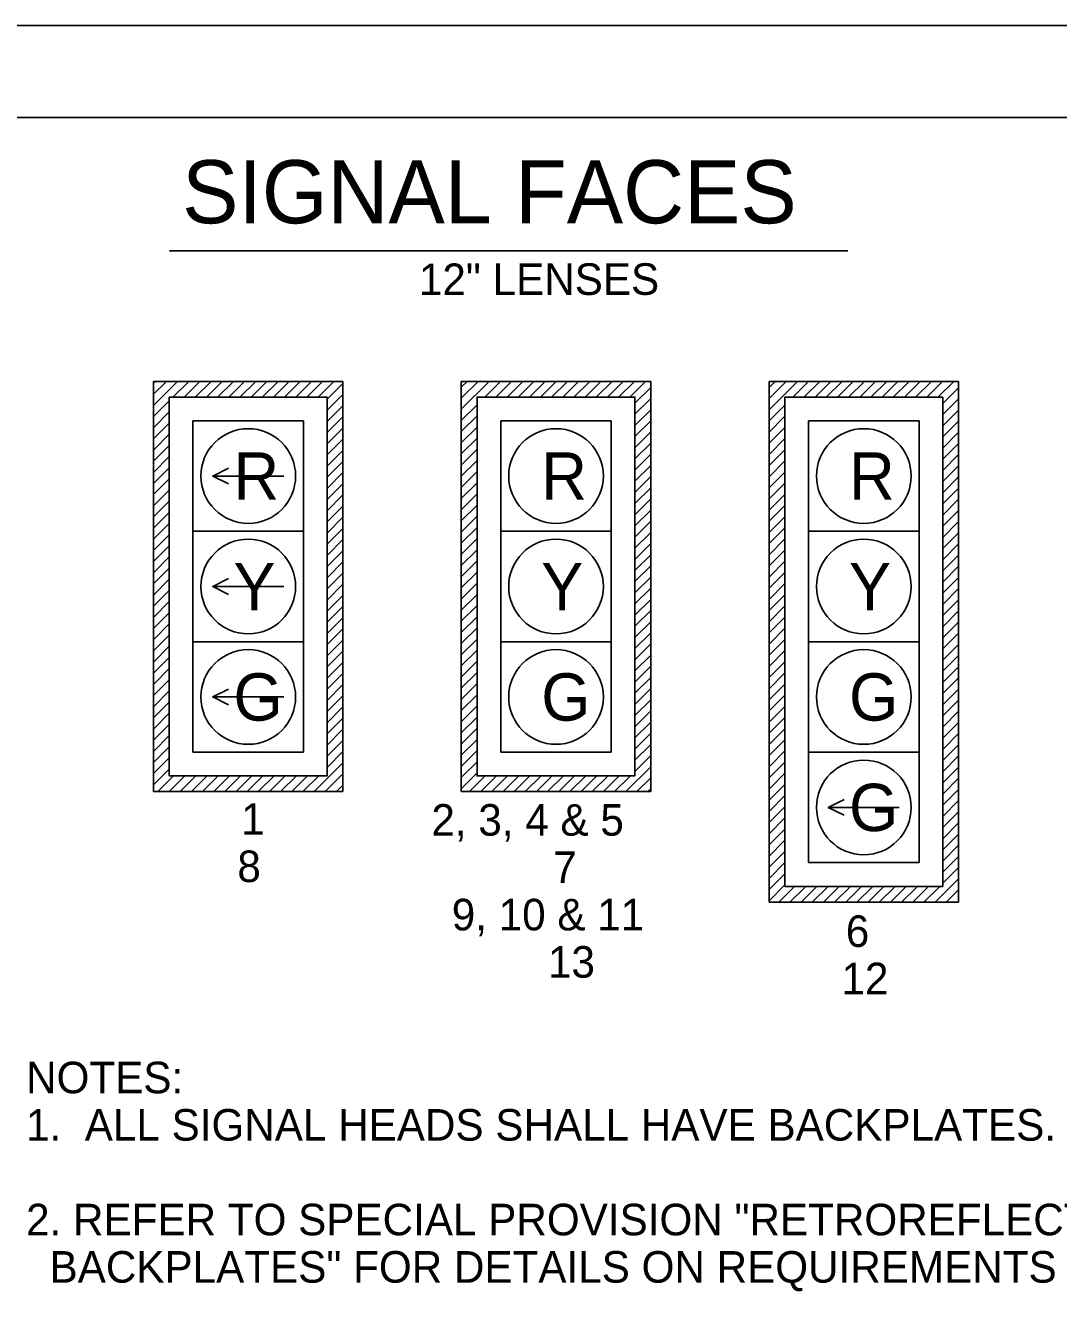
# Model space of a CAD drawing. Extents: x 660636 to 661659, y 641779 to 643841.
# Drawn here: x 660851.1 to 660982, y 642763.1 to 642924 of the extents above; entities that cross this region are included whole.
import ezdxf

# ---------------------------------------------------------------- set-up
doc = ezdxf.new("R2010")
doc.units = 0
for name, color, linetype in [('Default', 7, 'Continuous'), ('R_Border', 7, 'Continuous'), ('R_No Plot', 7, 'Continuous'), ('T_Drafting', 7, 'Continuous')]:
    doc.layers.add(name, color=color, linetype=linetype)

msp = doc.modelspace()

# ---------------------------------------------------------------- linework, layer by layer
at = {"layer": 'Default'}
msp.add_line((660869.32, 642895.44), (660955.26, 642895.44), dxfattribs=at)
at = {"layer": 'R_Border'}
msp.add_line((660695.76, 642912.31), (661644.3, 642912.31), dxfattribs=at)
at = {"layer": 'R_No Plot'}
msp.add_line((660658.55, 642924), (661658.55, 642924), dxfattribs=at)
msp.add_lwpolyline([(660658.53, 642924), (661658.55, 642924), (661658.55, 642283.98), (660658.53, 642283.98)], close=True, dxfattribs=at)
at = {"layer": 'T_Drafting'}
for p, q in [((660867.29, 642878.88), (660891.29, 642878.88)), ((660867.29, 642826.88), (660867.29, 642878.88)), ((660867.29, 642875.83), (660870.34, 642878.88)), ((660867.29, 642877.25), (660868.92, 642878.88)), ((660867.29, 642878.66), (660867.51, 642878.88)), ((660869.75, 642876.88), (660871.75, 642878.88)), ((660871.17, 642876.88), (660873.17, 642878.88)), ((660872.58, 642876.88), (660874.58, 642878.88)), ((660873.99, 642876.88), (660875.99, 642878.88)), ((660875.41, 642876.88), (660877.41, 642878.88)), ((660876.82, 642876.88), (660878.82, 642878.88)), ((660878.24, 642876.88), (660880.24, 642878.88)), ((660879.65, 642876.88), (660881.65, 642878.88)), ((660881.07, 642876.88), (660883.07, 642878.88)), ((660882.48, 642876.88), (660884.48, 642878.88)), ((660883.89, 642876.88), (660885.89, 642878.88)), ((660885.31, 642876.88), (660887.31, 642878.88)), ((660886.72, 642876.88), (660888.72, 642878.88)), ((660888.14, 642876.88), (660890.14, 642878.88)), ((660889.29, 642876.62), (660891.29, 642878.62)), ((660891.29, 642878.88), (660891.29, 642826.88)), ((660930.29, 642878.88), (660906.29, 642878.88)), ((660906.29, 642878.88), (660906.29, 642826.88)), ((660906.29, 642875.34), (660909.83, 642878.88)), ((660906.29, 642876.75), (660908.42, 642878.88)), ((660906.29, 642878.16), (660907.01, 642878.88)), ((660909.25, 642876.88), (660911.25, 642878.88)), ((660910.66, 642876.88), (660912.66, 642878.88)), ((660912.08, 642876.88), (660914.08, 642878.88)), ((660913.49, 642876.88), (660915.49, 642878.88)), ((660914.91, 642876.88), (660916.91, 642878.88)), ((660916.32, 642876.88), (660918.32, 642878.88)), ((660917.73, 642876.88), (660919.73, 642878.88)), ((660919.15, 642876.88), (660921.15, 642878.88)), ((660920.56, 642876.88), (660922.56, 642878.88)), ((660921.98, 642876.88), (660923.98, 642878.88)), ((660923.39, 642876.88), (660925.39, 642878.88)), ((660924.81, 642876.88), (660926.81, 642878.88)), ((660926.22, 642876.88), (660928.22, 642878.88)), ((660927.63, 642876.88), (660929.63, 642878.88)), ((660930.29, 642826.88), (660930.29, 642878.88)), ((660969.29, 642878.88), (660945.29, 642878.88)), ((660945.29, 642878.88), (660945.29, 642812.88)), ((660945.29, 642875.29), (660948.88, 642878.88)), ((660945.29, 642876.7), (660947.47, 642878.88)), ((660945.29, 642878.12), (660946.05, 642878.88)), ((660948.3, 642876.88), (660950.3, 642878.88)), ((660949.71, 642876.88), (660951.71, 642878.88)), ((660951.12, 642876.88), (660953.12, 642878.88)), ((660952.54, 642876.88), (660954.54, 642878.88)), ((660953.95, 642876.88), (660955.95, 642878.88)), ((660955.37, 642876.88), (660957.37, 642878.88)), ((660956.78, 642876.88), (660958.78, 642878.88)), ((660958.19, 642876.88), (660960.19, 642878.88)), ((660959.61, 642876.88), (660961.61, 642878.88)), ((660961.02, 642876.88), (660963.02, 642878.88)), ((660962.44, 642876.88), (660964.44, 642878.88)), ((660963.85, 642876.88), (660965.85, 642878.88)), ((660965.27, 642876.88), (660967.27, 642878.88)), ((660966.68, 642876.88), (660968.68, 642878.88)), ((660969.29, 642812.88), (660969.29, 642878.88)), ((660889.29, 642875.21), (660891.29, 642877.21)), ((660928.29, 642876.12), (660930.29, 642878.12)), ((660967.29, 642876.08), (660969.29, 642878.08)), ((660867.29, 642874.42), (660869.29, 642876.42)), ((660889.29, 642873.79), (660891.29, 642875.79)), ((660906.29, 642873.92), (660908.29, 642875.92)), ((660928.29, 642874.71), (660930.29, 642876.71)), ((660945.29, 642873.88), (660947.29, 642875.88)), ((660967.29, 642874.66), (660969.29, 642876.66)), ((660867.29, 642873), (660869.29, 642875)), ((660872.29, 642873.88), (660886.29, 642873.88)), ((660872.29, 642873.88), (660872.29, 642859.88)), ((660886.29, 642873.88), (660886.29, 642859.88)), ((660889.29, 642872.38), (660891.29, 642874.38)), ((660906.29, 642872.51), (660908.29, 642874.51)), ((660911.29, 642873.88), (660925.29, 642873.88)), ((660911.29, 642873.88), (660911.29, 642859.88)), ((660925.29, 642873.88), (660925.29, 642859.88)), ((660928.29, 642873.29), (660930.29, 642875.29)), ((660928.29, 642871.88), (660930.29, 642873.88)), ((660945.29, 642872.46), (660947.29, 642874.46)), ((660950.29, 642873.88), (660964.29, 642873.88)), ((660950.29, 642873.88), (660950.29, 642859.88)), ((660964.29, 642873.88), (660964.29, 642859.88)), ((660967.29, 642873.25), (660969.29, 642875.25)), ((660967.29, 642871.83), (660969.29, 642873.83)), ((660867.29, 642871.59), (660869.29, 642873.59)), ((660867.29, 642870.18), (660869.29, 642872.18)), ((660889.29, 642870.96), (660891.29, 642872.96)), ((660906.29, 642871.09), (660908.29, 642873.09)), ((660928.29, 642870.47), (660930.29, 642872.47)), ((660945.29, 642871.05), (660947.29, 642873.05)), ((660967.29, 642870.42), (660969.29, 642872.42)), ((660867.29, 642868.76), (660869.29, 642870.76)), ((660889.29, 642869.55), (660891.29, 642871.55)), ((660906.29, 642869.68), (660908.29, 642871.68)), ((660928.29, 642869.05), (660930.29, 642871.05)), ((660945.29, 642869.63), (660947.29, 642871.63)), ((660967.29, 642869.01), (660969.29, 642871.01)), ((660867.29, 642867.35), (660869.29, 642869.35)), ((660889.29, 642868.13), (660891.29, 642870.13)), ((660906.29, 642868.27), (660908.29, 642870.27)), ((660928.29, 642867.64), (660930.29, 642869.64)), ((660945.29, 642868.22), (660947.29, 642870.22)), ((660967.29, 642867.59), (660969.29, 642869.59)), ((660867.29, 642865.93), (660869.29, 642867.93)), ((660889.29, 642866.72), (660891.29, 642868.72)), ((660906.29, 642866.85), (660908.29, 642868.85)), ((660906.29, 642865.44), (660908.29, 642867.44)), ((660928.29, 642866.22), (660930.29, 642868.22)), ((660945.29, 642866.8), (660947.29, 642868.8)), ((660945.29, 642865.39), (660947.29, 642867.39)), ((660967.29, 642866.18), (660969.29, 642868.18)), ((660867.29, 642864.52), (660869.29, 642866.52)), ((660883.79, 642866.88), (660874.79, 642866.88)), ((660889.29, 642865.31), (660891.29, 642867.31)), ((660889.29, 642863.89), (660891.29, 642865.89)), ((660906.29, 642864.02), (660908.29, 642866.02)), ((660928.29, 642864.81), (660930.29, 642866.81)), ((660945.29, 642863.98), (660947.29, 642865.98)), ((660967.29, 642864.76), (660969.29, 642866.76)), ((660867.29, 642863.11), (660869.29, 642865.11)), ((660889.29, 642862.48), (660891.29, 642864.48)), ((660906.29, 642862.61), (660908.29, 642864.61)), ((660928.29, 642863.4), (660930.29, 642865.4)), ((660945.29, 642862.56), (660947.29, 642864.56)), ((660967.29, 642863.35), (660969.29, 642865.35)), ((660867.29, 642861.69), (660869.29, 642863.69)), ((660889.29, 642861.06), (660891.29, 642863.06)), ((660906.29, 642861.19), (660908.29, 642863.19)), ((660928.29, 642861.98), (660930.29, 642863.98)), ((660928.29, 642860.57), (660930.29, 642862.57)), ((660945.29, 642861.15), (660947.29, 642863.15)), ((660967.29, 642861.93), (660969.29, 642863.93)), ((660967.29, 642860.52), (660969.29, 642862.52)), ((660867.29, 642860.28), (660869.29, 642862.28)), ((660889.29, 642859.65), (660891.29, 642861.65)), ((660906.29, 642859.78), (660908.29, 642861.78)), ((660928.29, 642859.15), (660930.29, 642861.15)), ((660945.29, 642859.73), (660947.29, 642861.73)), ((660967.29, 642859.11), (660969.29, 642861.11)), ((660867.29, 642858.86), (660869.29, 642860.86)), ((660867.29, 642857.45), (660869.29, 642859.45)), ((660872.29, 642859.88), (660886.29, 642859.88)), ((660872.29, 642859.88), (660872.29, 642845.88)), ((660886.29, 642859.88), (660886.29, 642845.88)), ((660889.29, 642858.24), (660891.29, 642860.24)), ((660906.29, 642858.37), (660908.29, 642860.37)), ((660911.29, 642859.88), (660925.29, 642859.88)), ((660911.29, 642859.88), (660911.29, 642845.88)), ((660925.29, 642859.88), (660925.29, 642845.88)), ((660928.29, 642857.74), (660930.29, 642859.74)), ((660945.29, 642858.32), (660947.29, 642860.32)), ((660950.29, 642859.88), (660964.29, 642859.88)), ((660950.29, 642859.88), (660950.29, 642845.88)), ((660964.29, 642859.88), (660964.29, 642845.88)), ((660967.29, 642857.69), (660969.29, 642859.69)), ((660867.29, 642856.03), (660869.29, 642858.03)), ((660889.29, 642856.82), (660891.29, 642858.82)), ((660906.29, 642856.95), (660908.29, 642858.95)), ((660928.29, 642856.32), (660930.29, 642858.32)), ((660945.29, 642856.91), (660947.29, 642858.91)), ((660967.29, 642856.28), (660969.29, 642858.28)), ((660867.29, 642854.62), (660869.29, 642856.62)), ((660889.29, 642855.41), (660891.29, 642857.41)), ((660906.29, 642855.54), (660908.29, 642857.54)), ((660906.29, 642854.12), (660908.29, 642856.12)), ((660928.29, 642854.91), (660930.29, 642856.91)), ((660945.29, 642855.49), (660947.29, 642857.49)), ((660945.29, 642854.08), (660947.29, 642856.08)), ((660967.29, 642854.86), (660969.29, 642856.86)), ((660867.29, 642853.21), (660869.29, 642855.21)), ((660889.29, 642853.99), (660891.29, 642855.99)), ((660889.29, 642852.58), (660891.29, 642854.58)), ((660906.29, 642852.71), (660908.29, 642854.71)), ((660928.29, 642853.5), (660930.29, 642855.5)), ((660945.29, 642852.66), (660947.29, 642854.66)), ((660967.29, 642853.45), (660969.29, 642855.45)), ((660867.29, 642851.79), (660869.29, 642853.79)), ((660883.79, 642852.88), (660874.79, 642852.88)), ((660889.29, 642851.16), (660891.29, 642853.16)), ((660906.29, 642851.29), (660908.29, 642853.29)), ((660928.29, 642852.08), (660930.29, 642854.08)), ((660945.29, 642851.25), (660947.29, 642853.25)), ((660967.29, 642852.04), (660969.29, 642854.04)), ((660867.29, 642850.38), (660869.29, 642852.38)), ((660889.29, 642849.75), (660891.29, 642851.75)), ((660906.29, 642849.88), (660908.29, 642851.88)), ((660928.29, 642850.67), (660930.29, 642852.67)), ((660928.29, 642849.25), (660930.29, 642851.25)), ((660945.29, 642849.83), (660947.29, 642851.83)), ((660967.29, 642850.62), (660969.29, 642852.62)), ((660867.29, 642848.96), (660869.29, 642850.96)), ((660889.29, 642848.34), (660891.29, 642850.34)), ((660906.29, 642848.47), (660908.29, 642850.47)), ((660928.29, 642847.84), (660930.29, 642849.84)), ((660945.29, 642848.42), (660947.29, 642850.42)), ((660967.29, 642849.21), (660969.29, 642851.21)), ((660967.29, 642847.79), (660969.29, 642849.79)), ((660867.29, 642847.55), (660869.29, 642849.55)), ((660867.29, 642846.13), (660869.29, 642848.13)), ((660889.29, 642846.92), (660891.29, 642848.92)), ((660906.29, 642847.05), (660908.29, 642849.05)), ((660928.29, 642846.42), (660930.29, 642848.42)), ((660945.29, 642847.01), (660947.29, 642849.01)), ((660967.29, 642846.38), (660969.29, 642848.38)), ((660867.29, 642844.72), (660869.29, 642846.72)), ((660889.29, 642845.51), (660891.29, 642847.51)), ((660906.29, 642845.64), (660908.29, 642847.64)), ((660928.29, 642845.01), (660930.29, 642847.01)), ((660945.29, 642845.59), (660947.29, 642847.59)), ((660967.29, 642844.96), (660969.29, 642846.96)), ((660867.29, 642843.31), (660869.29, 642845.31)), ((660872.29, 642845.88), (660886.29, 642845.88)), ((660872.29, 642845.88), (660872.29, 642831.88)), ((660886.29, 642845.88), (660886.29, 642831.88)), ((660889.29, 642844.09), (660891.29, 642846.09)), ((660906.29, 642844.22), (660908.29, 642846.22)), ((660906.29, 642842.81), (660908.29, 642844.81)), ((660911.29, 642845.88), (660925.29, 642845.88)), ((660911.29, 642845.88), (660911.29, 642831.88)), ((660925.29, 642845.88), (660925.29, 642831.88)), ((660928.29, 642843.6), (660930.29, 642845.6)), ((660945.29, 642844.18), (660947.29, 642846.18)), ((660950.29, 642845.88), (660964.29, 642845.88)), ((660950.29, 642845.88), (660950.29, 642831.88)), ((660964.29, 642845.88), (660964.29, 642831.88)), ((660967.29, 642843.55), (660969.29, 642845.55)), ((660867.29, 642841.89), (660869.29, 642843.89)), ((660889.29, 642842.68), (660891.29, 642844.68)), ((660889.29, 642841.26), (660891.29, 642843.26)), ((660906.29, 642841.4), (660908.29, 642843.4)), ((660928.29, 642842.18), (660930.29, 642844.18)), ((660945.29, 642842.76), (660947.29, 642844.76)), ((660945.29, 642841.35), (660947.29, 642843.35)), ((660967.29, 642842.14), (660969.29, 642844.14)), ((660867.29, 642840.48), (660869.29, 642842.48)), ((660889.29, 642839.85), (660891.29, 642841.85)), ((660906.29, 642839.98), (660908.29, 642841.98)), ((660928.29, 642840.77), (660930.29, 642842.77)), ((660945.29, 642839.93), (660947.29, 642841.93)), ((660967.29, 642840.72), (660969.29, 642842.72)), ((660867.29, 642839.06), (660869.29, 642841.06)), ((660889.29, 642838.44), (660891.29, 642840.44)), ((660906.29, 642838.57), (660908.29, 642840.57)), ((660928.29, 642839.35), (660930.29, 642841.35)), ((660945.29, 642838.52), (660947.29, 642840.52)), ((660967.29, 642839.31), (660969.29, 642841.31)), ((660867.29, 642837.65), (660869.29, 642839.65)), ((660883.79, 642838.88), (660874.79, 642838.88)), ((660889.29, 642837.02), (660891.29, 642839.02)), ((660906.29, 642837.15), (660908.29, 642839.15)), ((660928.29, 642837.94), (660930.29, 642839.94)), ((660928.29, 642836.53), (660930.29, 642838.53)), ((660945.29, 642837.11), (660947.29, 642839.11)), ((660967.29, 642837.89), (660969.29, 642839.89)), ((660967.29, 642836.48), (660969.29, 642838.48)), ((660867.29, 642836.24), (660869.29, 642838.24)), ((660867.29, 642834.82), (660869.29, 642836.82)), ((660889.29, 642835.61), (660891.29, 642837.61)), ((660906.29, 642835.74), (660908.29, 642837.74)), ((660928.29, 642835.11), (660930.29, 642837.11)), ((660945.29, 642835.69), (660947.29, 642837.69)), ((660967.29, 642835.06), (660969.29, 642837.06)), ((660867.29, 642833.41), (660869.29, 642835.41)), ((660889.29, 642834.19), (660891.29, 642836.19)), ((660906.29, 642834.32), (660908.29, 642836.32)), ((660928.29, 642833.7), (660930.29, 642835.7)), ((660945.29, 642834.28), (660947.29, 642836.28)), ((660967.29, 642833.65), (660969.29, 642835.65)), ((660867.29, 642831.99), (660869.29, 642833.99)), ((660889.29, 642832.78), (660891.29, 642834.78)), ((660906.29, 642832.91), (660908.29, 642834.91)), ((660928.29, 642832.28), (660930.29, 642834.28)), ((660945.29, 642832.86), (660947.29, 642834.86)), ((660967.29, 642832.24), (660969.29, 642834.24)), ((660867.29, 642830.58), (660869.29, 642832.58)), ((660889.29, 642831.37), (660891.29, 642833.37)), ((660889.29, 642829.95), (660891.29, 642831.95)), ((660906.29, 642831.5), (660908.29, 642833.5)), ((660906.29, 642830.08), (660908.29, 642832.08)), ((660928.29, 642830.87), (660930.29, 642832.87)), ((660945.29, 642831.45), (660947.29, 642833.45)), ((660945.29, 642830.04), (660947.29, 642832.04)), ((660967.29, 642830.82), (660969.29, 642832.82)), ((660867.29, 642829.16), (660869.29, 642831.16)), ((660872.29, 642831.88), (660886.29, 642831.88)), ((660887.63, 642826.88), (660891.29, 642830.54)), ((660906.29, 642828.67), (660908.29, 642830.67)), ((660911.29, 642831.88), (660925.29, 642831.88)), ((660928.29, 642829.45), (660930.29, 642831.45)), ((660945.29, 642828.62), (660947.29, 642830.62)), ((660950.29, 642831.88), (660964.29, 642831.88)), ((660950.29, 642831.88), (660950.29, 642817.88)), ((660964.29, 642831.88), (660964.29, 642817.88)), ((660967.29, 642829.41), (660969.29, 642831.41)), ((660867.29, 642827.75), (660869.29, 642829.75)), ((660867.84, 642826.88), (660869.84, 642828.88)), ((660869.25, 642826.88), (660871.25, 642828.88)), ((660870.66, 642826.88), (660872.66, 642828.88)), ((660872.08, 642826.88), (660874.08, 642828.88)), ((660873.49, 642826.88), (660875.49, 642828.88)), ((660874.91, 642826.88), (660876.91, 642828.88)), ((660876.32, 642826.88), (660878.32, 642828.88)), ((660877.74, 642826.88), (660879.74, 642828.88)), ((660879.15, 642826.88), (660881.15, 642828.88)), ((660880.56, 642826.88), (660882.56, 642828.88)), ((660881.98, 642826.88), (660883.98, 642828.88)), ((660883.39, 642826.88), (660885.39, 642828.88)), ((660884.81, 642826.88), (660886.81, 642828.88)), ((660886.22, 642826.88), (660888.22, 642828.88)), ((660889.05, 642826.88), (660891.29, 642829.12)), ((660906.29, 642827.25), (660908.29, 642829.25)), ((660907.33, 642826.88), (660909.33, 642828.88)), ((660908.75, 642826.88), (660910.75, 642828.88)), ((660910.16, 642826.88), (660912.16, 642828.88)), ((660911.58, 642826.88), (660913.58, 642828.88)), ((660912.99, 642826.88), (660914.99, 642828.88)), ((660914.4, 642826.88), (660916.4, 642828.88)), ((660915.82, 642826.88), (660917.82, 642828.88)), ((660917.23, 642826.88), (660919.23, 642828.88)), ((660918.65, 642826.88), (660920.65, 642828.88)), ((660920.06, 642826.88), (660922.06, 642828.88)), ((660921.47, 642826.88), (660923.47, 642828.88)), ((660922.89, 642826.88), (660924.89, 642828.88)), ((660924.3, 642826.88), (660926.3, 642828.88)), ((660925.72, 642826.88), (660927.72, 642828.88)), ((660927.13, 642826.88), (660930.29, 642830.04)), ((660945.29, 642827.21), (660947.29, 642829.21)), ((660967.29, 642827.99), (660969.29, 642829.99)), ((660890.46, 642826.88), (660891.29, 642827.71)), ((660928.55, 642826.88), (660930.29, 642828.63)), ((660929.96, 642826.88), (660930.29, 642827.21)), ((660945.29, 642825.79), (660947.29, 642827.79)), ((660967.29, 642826.58), (660969.29, 642828.58)), ((660967.29, 642825.17), (660969.29, 642827.17)), ((660891.29, 642826.88), (660867.29, 642826.88)), ((660906.29, 642826.88), (660930.29, 642826.88)), ((660945.29, 642824.38), (660947.29, 642826.38)), ((660967.29, 642823.75), (660969.29, 642825.75)), ((660945.29, 642822.96), (660947.29, 642824.96)), ((660961.79, 642824.88), (660952.79, 642824.88)), ((660967.29, 642822.34), (660969.29, 642824.34)), ((660945.29, 642821.55), (660947.29, 642823.55)), ((660967.29, 642820.92), (660969.29, 642822.92)), ((660945.29, 642820.14), (660947.29, 642822.14)), ((660945.29, 642818.72), (660947.29, 642820.72)), ((660967.29, 642819.51), (660969.29, 642821.51)), ((660945.29, 642817.31), (660947.29, 642819.31)), ((660967.29, 642818.09), (660969.29, 642820.09)), ((660945.29, 642815.89), (660947.29, 642817.89)), ((660950.29, 642817.88), (660964.29, 642817.88)), ((660967.29, 642816.68), (660969.29, 642818.68)), ((660945.29, 642814.48), (660947.29, 642816.48)), ((660966.32, 642812.88), (660969.29, 642815.85)), ((660967.29, 642815.27), (660969.29, 642817.27)), ((660945.29, 642813.06), (660947.29, 642815.06)), ((660946.52, 642812.88), (660948.52, 642814.88)), ((660947.93, 642812.88), (660949.93, 642814.88)), ((660949.35, 642812.88), (660951.35, 642814.88)), ((660950.76, 642812.88), (660952.76, 642814.88)), ((660952.18, 642812.88), (660954.18, 642814.88)), ((660953.59, 642812.88), (660955.59, 642814.88)), ((660955.01, 642812.88), (660957.01, 642814.88)), ((660956.42, 642812.88), (660958.42, 642814.88)), ((660957.83, 642812.88), (660959.83, 642814.88)), ((660959.25, 642812.88), (660961.25, 642814.88)), ((660960.66, 642812.88), (660962.66, 642814.88)), ((660962.08, 642812.88), (660964.08, 642814.88)), ((660963.49, 642812.88), (660965.49, 642814.88)), ((660964.91, 642812.88), (660966.91, 642814.88)), ((660967.73, 642812.88), (660969.29, 642814.44)), ((660945.29, 642812.88), (660969.29, 642812.88)), ((660969.15, 642812.88), (660969.29, 642813.02))]:
    msp.add_line(p, q, dxfattribs=at)
for points in [[(660869.29, 642876.88), (660889.29, 642876.88), (660889.29, 642828.88), (660869.29, 642828.88)], [(660928.29, 642828.88), (660928.29, 642876.88), (660908.29, 642876.88), (660908.29, 642828.88)], [(660967.29, 642876.88), (660947.29, 642876.88), (660947.29, 642814.88), (660967.29, 642814.88)]]:
    msp.add_lwpolyline(points, close=True, dxfattribs=at)
for points in [[(660876.79, 642867.88), (660874.79, 642866.88), (660876.79, 642865.88)], [(660876.79, 642853.88), (660874.79, 642852.88), (660876.79, 642851.88)], [(660876.79, 642839.88), (660874.79, 642838.88), (660876.79, 642837.88)], [(660954.79, 642825.88), (660952.79, 642824.88), (660954.79, 642823.88)]]:
    msp.add_lwpolyline(points, dxfattribs=at)
for centre in [(660879.29, 642866.88), (660918.29, 642866.88), (660957.29, 642866.88), (660879.29, 642852.88), (660918.29, 642852.88), (660957.29, 642852.88), (660879.29, 642838.88), (660918.29, 642838.88), (660957.29, 642838.88), (660957.29, 642824.88)]:
    msp.add_circle(centre, 6, dxfattribs=at)

# ---------------------------------------------------------------- texts
at = {"layer": 'Default'}
for s, height, p in [('SIGNAL FACES', 8, (660870.91, 642898.91)), ('1', 4, (660878.39, 642821.42)), ('2, 3, 4 & 5', 4, (660902.5, 642821.3)), ('8', 4, (660877.91, 642815.42)), ('7', 4, (660917.93, 642815.3)), ('9, 10 & 11', 4, (660905.08, 642809.3)), ('6', 4, (660955.01, 642807.2)), ('13', 4, (660917.27, 642803.3)), ('12', 4, (660954.46, 642801.2)), ('NOTES:', 4, (660851.14, 642788.65)), ('1.  ALL SIGNAL HEADS SHALL HAVE BACKPLATES.', 4, (660851.14, 642782.65)), ('2. REFER TO SPECIAL PROVISION "RETROREFLECTIVE', 4, (660851.14, 642770.65)), ('  BACKPLATES" FOR DETAILS ON REQUIREMENTS FOR', 4, (660851.14, 642764.65))]:
    msp.add_text(s, height=height, dxfattribs=at).set_placement(p)
at = {"layer": 'T_Drafting'}
msp.add_text('12" LENSES', height=4, rotation=0.072, dxfattribs=at).set_placement((660900.92, 642889.81))
for s, p in [('R', (660877.42, 642863.88)), ('R', (660916.42, 642863.88)), ('R', (660955.42, 642863.88)), ('Y', (660877.4, 642849.88)), ('Y', (660916.4, 642849.88)), ('Y', (660955.4, 642849.88)), ('G', (660877.42, 642835.88)), ('G', (660916.42, 642835.88)), ('G', (660955.42, 642835.88)), ('G', (660955.42, 642821.88))]:
    msp.add_text(s, height=6, dxfattribs=at).set_placement(p)

doc.saveas('drawing.dxf')
